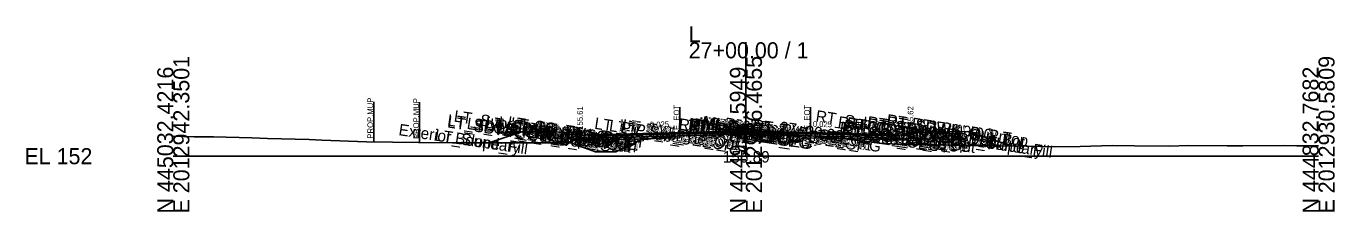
# Model space of a CAD drawing. Extents: x -26 to 4203, y -10 to 9526.
# Drawn here: x 974.3 to 1202.8, y 6990.3 to 7022.7 of the extents above; entities that cross this region are included whole.
import ezdxf

# ---------------------------------------------------------------- set-up
doc = ezdxf.new("R2010")
doc.units = 0
for name, color, linetype in [('Default', 7, 'Continuous'), ('Exist CMT Pavement', 7, 'Continuous'), ('Exist Cross Section Cell', 7, 'Continuous'), ('Exist XS Center Line Elevation Label', 7, 'Continuous'), ('Exist XS Ground Line', 7, 'Continuous'), ('Prop CMT Conc Surface', 7, 'Continuous'), ('Prop CMT Concrete Structures', 7, 'Continuous'), ('Prop CMT Pvmt Course 1', 7, 'Continuous'), ('Prop CMT Pvmt Course 1 CG', 7, 'Continuous'), ('Prop CMT Pvmt Course 1 Wedge', 7, 'Continuous'), ('Prop CMT Pvmt Course 2', 7, 'Continuous'), ('Prop CMT Pvmt Course 2 Wedge', 7, 'Continuous'), ('Prop CMT Pvmt Course 3', 7, 'Continuous'), ('Prop CMT Pvmt Course 3 Wedge', 7, 'Continuous'), ('Prop CMT Pvmt Surface', 7, 'Continuous'), ('Prop CMT Pvmt Wedge Surface 1', 7, 'Continuous'), ('Prop CMT Pvmt Wedge Surface 2', 7, 'Continuous'), ('Prop CMT Pvmt Wedge Surface 3', 7, 'Continuous'), ('Prop CMT Slope Grass', 7, 'Continuous'), ('Prop CMT Subgrade Earthwork', 7, 'Continuous'), ('Prop XS Hydro Elevations', 7, 'Continuous'), ('Prop XS Label Text', 7, 'Continuous'), ('Prop XS SE Text', 7, 'Continuous'), ('Prop XS Side Slope Text', 7, 'Continuous'), ('Scratch_Level_0', 7, 'Continuous')]:
    doc.layers.add(name, color=color, linetype=linetype)

msp = doc.modelspace()

# ---------------------------------------------------------------- linework, layer by layer
at = {"layer": 'Exist CMT Pavement'}
for points in [[(1100, 7003.89), (1099.36, 7003.89), (1099.31, 7003.89), (1099.22, 7003.88), (1097.54, 7003.82), (1097.16, 7003.8), (1095.03, 7003.75), (1092.66, 7003.69), (1092.55, 7003.69), (1092.45, 7003.68), (1090.5, 7003.6), (1090.05, 7003.58), (1090.02, 7003.58), (1089.99, 7003.58), (1088.48, 7003.54)], [(1100, 7003.89), (1100.04, 7003.89), (1100.62, 7003.87), (1102.51, 7003.83), (1104.24, 7003.8), (1105.04, 7003.78), (1105.93, 7003.75), (1107.53, 7003.69), (1108.58, 7003.66), (1110.05, 7003.62), (1110.82, 7003.56), (1111.06, 7003.55), (1111.26, 7003.53), (1111.26, 7003.53)]]:
    msp.add_lwpolyline(points, dxfattribs=at)
at = {"layer": 'Exist Cross Section Cell'}
for p, q in [((1100, 7000), (1100, 7019.86)), ((1000, 7000), (1100, 7000)), ((1100, 7000), (1200, 7000))]:
    msp.add_line(p, q, dxfattribs=at)
at = {"layer": 'Exist XS Ground Line'}
msp.add_lwpolyline([(1000, 7003.5), (1003.67, 7003.39), (1007, 7003.38), (1013.69, 7003.2), (1016.46, 7003.08), (1023.71, 7002.91), (1025.92, 7002.78), (1033.73, 7002.51), (1042.83, 7002.41), (1048.74, 7002.32), (1050.19, 7002.32), (1055.64, 7002.32), (1065.4, 7002.32), (1067.1, 7002.32), (1069.4, 7002.32), (1071.14, 7001.69), (1073.74, 7000.76), (1075.74, 7000.76), (1077.27, 7000.78), (1081.72, 7002.84), (1082.64, 7002.94), (1083.4, 7003.02), (1087.18, 7003.42), (1087.87, 7003.51), (1088.48, 7003.54), (1090.05, 7003.58), (1090.5, 7003.6), (1092.66, 7003.69), (1095.03, 7003.75), (1097.16, 7003.8), (1097.54, 7003.82), (1099.31, 7003.89), (1100.04, 7003.89), (1100.62, 7003.87), (1102.51, 7003.83), (1104.24, 7003.8), (1105.04, 7003.78), (1105.93, 7003.75), (1107.53, 7003.69), (1108.58, 7003.66), (1110.05, 7003.62), (1111.26, 7003.53), (1116.63, 7003.08), (1121.51, 7002.48), (1123.74, 7002.22), (1131, 7001.97), (1139.45, 7001.85), (1143.93, 7001.82), (1148.91, 7001.74), (1153.95, 7001.61), (1158.37, 7001.68), (1163.97, 7001.89), (1167.83, 7001.81), (1173.99, 7001.76), (1177.29, 7001.85), (1184.01, 7001.79), (1186.75, 7001.78), (1194.03, 7001.84), (1196.21, 7001.83), (1200, 7001.81)], dxfattribs=at)
at = {"layer": 'Prop CMT Conc Surface'}
for points in [[(1071.03, 7003.61), (1071.03, 7004.11), (1070.53, 7004.11)], [(1073.04, 7003.74), (1071.03, 7003.61)], [(1126.75, 7003.75), (1128.75, 7003.62)], [(1128.75, 7003.62), (1128.75, 7004.12), (1129.25, 7004.12)], [(1133.25, 7004.21), (1138.25, 7004.31)]]:
    msp.add_lwpolyline(points, dxfattribs=at)
at = {"layer": 'Prop CMT Concrete Structures'}
for points in [[(1102, 7004.36), (1101.99, 7004.53), (1101.24, 7004.78), (1100, 7004.81), (1098.76, 7004.78), (1098.01, 7004.53), (1098, 7004.36)], [(1073.04, 7003.74), (1071.03, 7003.61), (1071.03, 7004.11), (1070.53, 7004.11)], [(1070.53, 7004.11), (1070.53, 7003.09), (1073.04, 7003.16)], [(1073.04, 7003.16), (1073.04, 7003.74)], [(1098, 7004.36), (1100, 7004.41), (1102, 7004.36)], [(1126.75, 7003.75), (1128.75, 7003.62), (1128.75, 7004.12), (1129.25, 7004.12)], [(1129.25, 7004.12), (1129.25, 7003.1), (1126.75, 7003.16)], [(1126.75, 7003.16), (1126.75, 7003.75)], [(1138.25, 7004.31), (1133.25, 7004.21)], [(1133.25, 7004.21), (1133.25, 7003.87)], [(1133.25, 7003.87), (1138.25, 7003.97)], [(1138.25, 7003.97), (1138.25, 7004.31)]]:
    msp.add_lwpolyline(points, dxfattribs=at)
at = {"layer": 'Prop CMT Pvmt Course 1'}
for points in [[(1100, 7004.41), (1073.04, 7003.74)], [(1073.04, 7003.49), (1088.48, 7003.88)], [(1073.04, 7003.74), (1073.04, 7003.49)], [(1088.48, 7004), (1100, 7004.29)], [(1088.48, 7003.88), (1088.48, 7004)], [(1100, 7004.16), (1100, 7004.41)], [(1100, 7004.41), (1126.75, 7003.75)], [(1100, 7004.16), (1100, 7004.41)], [(1100, 7004.29), (1100, 7004.16), (1100, 7004.16)], [(1111.26, 7004.01), (1100, 7004.29)], [(1100, 7004.29), (1100, 7004.16), (1100, 7004.16)], [(1111.26, 7003.88), (1111.26, 7004.01)], [(1126.75, 7003.5), (1111.26, 7003.88)], [(1126.75, 7003.75), (1126.75, 7003.5)]]:
    msp.add_lwpolyline(points, dxfattribs=at)
at = {"layer": 'Prop CMT Pvmt Course 1 CG'}
for points in [[(1073.04, 7003.16), (1070.03, 7003.08), (1069.69, 7002.74)], [(1069.69, 7002.74), (1073.04, 7002.82)], [(1073.04, 7002.82), (1073.04, 7003.16)], [(1126.75, 7003.16), (1129.75, 7003.09), (1130.09, 7002.75)], [(1126.75, 7002.83), (1126.75, 7003.16)], [(1130.09, 7002.75), (1126.75, 7002.83)]]:
    msp.add_lwpolyline(points, dxfattribs=at)
at = {"layer": 'Prop CMT Pvmt Course 1 Wedge'}
for points in [[(1088.48, 7004), (1089.99, 7004.04), (1090.02, 7004.04), (1090.05, 7004.04), (1090.5, 7004.05), (1092.45, 7004.1), (1092.55, 7004.1), (1092.66, 7004.11), (1095.03, 7004.17), (1097.16, 7004.22), (1097.54, 7004.23), (1099.22, 7004.27), (1099.31, 7004.27), (1099.36, 7004.27), (1100, 7004.29)], [(1100, 7004.16), (1099.36, 7004.15), (1099.31, 7004.15), (1099.22, 7004.15), (1097.54, 7004.1), (1097.16, 7004.09), (1095.03, 7004.04), (1092.66, 7003.98), (1092.55, 7003.98), (1092.45, 7003.98), (1090.5, 7003.93), (1090.05, 7003.92), (1090.02, 7003.92), (1089.99, 7003.91), (1088.48, 7003.88)], [(1088.48, 7003.88), (1088.48, 7004)], [(1100, 7004.29), (1100, 7004.16)], [(1100, 7004.29), (1100.04, 7004.29), (1100.62, 7004.27), (1102.51, 7004.23), (1104.24, 7004.18), (1105.04, 7004.16), (1105.93, 7004.14), (1107.53, 7004.1), (1108.58, 7004.08), (1110.05, 7004.04), (1110.82, 7004.02), (1111.06, 7004.01), (1111.26, 7004.01), (1111.26, 7004.01)], [(1100, 7004.16), (1100, 7004.29)], [(1111.26, 7003.88), (1111.26, 7003.88), (1111.06, 7003.89), (1110.82, 7003.89), (1110.05, 7003.91), (1108.58, 7003.95), (1107.53, 7003.98), (1105.93, 7004.02), (1105.04, 7004.04), (1104.24, 7004.06), (1102.51, 7004.1), (1100.62, 7004.15), (1100.04, 7004.16), (1100, 7004.16)], [(1111.26, 7004.01), (1111.26, 7003.88)]]:
    msp.add_lwpolyline(points, dxfattribs=at)
at = {"layer": 'Prop CMT Pvmt Course 2'}
for points in [[(1088.48, 7003.88), (1073.04, 7003.49)], [(1073.04, 7003.16), (1088.48, 7003.54)], [(1073.04, 7003.49), (1073.04, 7003.16)], [(1088.48, 7003.54), (1088.48, 7003.88)], [(1111.26, 7003.55), (1111.26, 7003.88)], [(1111.26, 7003.88), (1126.75, 7003.5)], [(1126.75, 7003.16), (1111.26, 7003.55)], [(1126.75, 7003.5), (1126.75, 7003.16)]]:
    msp.add_lwpolyline(points, dxfattribs=at)
at = {"layer": 'Prop CMT Pvmt Course 2 Wedge'}
for points in [[(1088.48, 7003.88), (1089.99, 7003.91), (1090.02, 7003.92), (1090.05, 7003.92), (1090.5, 7003.93), (1092.45, 7003.98), (1092.55, 7003.98), (1092.66, 7003.98), (1095.03, 7004.04), (1097.16, 7004.09), (1097.54, 7004.1), (1099.22, 7004.15), (1099.31, 7004.15), (1099.36, 7004.15), (1100, 7004.16)], [(1100, 7003.89), (1099.36, 7003.89), (1099.31, 7003.89), (1099.22, 7003.88), (1097.54, 7003.82), (1097.16, 7003.8), (1095.03, 7003.75), (1092.66, 7003.69), (1092.55, 7003.69), (1092.45, 7003.68), (1090.5, 7003.6), (1090.05, 7003.58), (1090.02, 7003.58), (1089.99, 7003.58), (1089.94, 7003.58), (1088.48, 7003.54)], [(1088.48, 7003.54), (1088.48, 7003.88)], [(1100, 7004.16), (1100.04, 7004.16), (1100.62, 7004.15), (1102.51, 7004.1), (1104.24, 7004.06), (1105.04, 7004.04), (1105.93, 7004.02), (1107.53, 7003.98), (1108.58, 7003.95), (1110.05, 7003.91), (1110.82, 7003.89), (1111.06, 7003.89), (1111.26, 7003.88), (1111.26, 7003.88)], [(1100, 7003.89), (1100, 7004.16)], [(1100, 7004.16), (1100, 7003.89)], [(1111.26, 7003.55), (1111.26, 7003.55), (1111.06, 7003.56), (1110.86, 7003.56), (1110.82, 7003.56), (1110.05, 7003.62), (1108.58, 7003.66), (1107.53, 7003.69), (1105.93, 7003.75), (1105.04, 7003.78), (1104.24, 7003.8), (1102.51, 7003.83), (1100.62, 7003.87), (1100.04, 7003.89), (1100, 7003.89)], [(1111.26, 7003.88), (1111.26, 7003.55)]]:
    msp.add_lwpolyline(points, dxfattribs=at)
at = {"layer": 'Prop CMT Pvmt Course 3'}
for points in [[(1088.48, 7003.54), (1073.04, 7003.16)], [(1073.04, 7002.82), (1088.48, 7003.21)], [(1073.04, 7003.16), (1073.04, 7002.82)], [(1088.48, 7003.21), (1088.48, 7003.54)], [(1111.26, 7003.55), (1126.75, 7003.16)], [(1111.26, 7003.22), (1111.26, 7003.55)], [(1126.75, 7002.83), (1111.26, 7003.22)], [(1126.75, 7003.16), (1126.75, 7002.83)]]:
    msp.add_lwpolyline(points, dxfattribs=at)
at = {"layer": 'Prop CMT Pvmt Course 3 Wedge'}
for points in [[(1088.48, 7003.54), (1089.99, 7003.58), (1090, 7003.58)], [(1090, 7003.58), (1089.99, 7003.58), (1088.48, 7003.54)], [(1088.48, 7003.54), (1088.48, 7003.54)], [(1111.26, 7003.53), (1111.26, 7003.53), (1111.06, 7003.55), (1110.87, 7003.56)], [(1110.87, 7003.56), (1111.06, 7003.55)], [(1111.06, 7003.55), (1111.26, 7003.55), (1111.26, 7003.55)], [(1111.26, 7003.55), (1111.26, 7003.53)]]:
    msp.add_lwpolyline(points, dxfattribs=at)
at = {"layer": 'Prop CMT Pvmt Surface'}
for points in [[(1100, 7004.41), (1073.04, 7003.74)], [(1100, 7004.41), (1126.75, 7003.75)]]:
    msp.add_lwpolyline(points, dxfattribs=at)
at = {"layer": 'Prop CMT Pvmt Wedge Surface 1'}
for points in [[(1088.48, 7003.88), (1073.04, 7003.49)], [(1073.04, 7003.49), (1073.04, 7003.74)], [(1100, 7004.29), (1088.48, 7004)], [(1088.48, 7004), (1088.48, 7003.88)], [(1100, 7004.29), (1111.26, 7004.01)], [(1111.26, 7004.01), (1111.26, 7003.88)], [(1111.26, 7003.88), (1126.75, 7003.5)], [(1126.75, 7003.5), (1126.75, 7003.75)]]:
    msp.add_lwpolyline(points, dxfattribs=at)
at = {"layer": 'Prop CMT Pvmt Wedge Surface 2'}
for points in [[(1100, 7004.16), (1073.04, 7003.49)], [(1073.04, 7003.49), (1073.04, 7003.74)], [(1100, 7004.16), (1126.75, 7003.5)], [(1126.75, 7003.5), (1126.75, 7003.75)]]:
    msp.add_lwpolyline(points, dxfattribs=at)
at = {"layer": 'Prop CMT Pvmt Wedge Surface 3'}
for points in [[(1100, 7003.83), (1073.04, 7003.16)], [(1073.04, 7003.16), (1073.04, 7003.74)], [(1100, 7003.83), (1126.75, 7003.16)], [(1126.75, 7003.16), (1126.75, 7003.75)]]:
    msp.add_lwpolyline(points, dxfattribs=at)
at = {"layer": 'Prop CMT Slope Grass'}
for points in [[(1070.53, 7004.11), (1061.03, 7004.3), (1055.09, 7002.32)], [(1129.25, 7004.12), (1138.75, 7004.31), (1146.33, 7001.78)]]:
    msp.add_lwpolyline(points, dxfattribs=at)
at = {"layer": 'Prop CMT Subgrade Earthwork'}
for points in [[(1073.04, 7002.82), (1069.69, 7002.74), (1068.28, 7004.16)], [(1088.48, 7003.21), (1073.04, 7002.82)], [(1088.48, 7003.21), (1088.49, 7003.54)], [(1111.26, 7003.22), (1111.25, 7003.54)], [(1111.26, 7003.22), (1126.75, 7002.83)], [(1126.75, 7002.83), (1130.09, 7002.75), (1131.51, 7004.16)]]:
    msp.add_lwpolyline(points, dxfattribs=at)
at = {"layer": 'Prop XS Label Text'}
for p, q in [((1035, 7009.49), (1035, 7002.49)), ((1043, 7009.41), (1043, 7002.41)), ((1088.48, 7008.54), (1088.48, 7003.54)), ((1111.26, 7008.54), (1111.26, 7003.53))]:
    msp.add_line(p, q, dxfattribs=at)

# ---------------------------------------------------------------- texts
at = {"layer": 'Default'}
msp.add_text('-', height=0.0001, dxfattribs=at).set_placement((1000, 7000))
at = {"layer": 'Exist Cross Section Cell'}
for s, p in [('L', (1090, 7019.86)), ('27+00.00 / 1', (1090, 7017.06)), ('EL 152', (974, 6998.6))]:
    msp.add_text(s, height=2.8, dxfattribs=at).set_placement(p)
for s, p in [('E 2012942.3501', (1002.8, 6990)), ('E 2012936.4655', (1102.8, 6990)), ('E 2012930.5809', (1202.8, 6990)), ('N 445032.4216', (1000, 6990)), ('N 444932.5949', (1100, 6990)), ('N 444832.7682', (1200, 6990))]:
    msp.add_text(s, height=2.8, rotation=90, dxfattribs=at).set_placement(p)
at = {"layer": 'Exist XS Center Line Elevation Label'}
msp.add_text('155.89', height=2, dxfattribs=at).set_placement((1095.97, 6998.89))
at = {"layer": 'Prop XS Hydro Elevations'}
for s, p in [('155.61', (1071.53, 7004.61)), ('155.62', (1129.25, 7004.62))]:
    msp.add_text(s, height=1, rotation=90, dxfattribs=at).set_placement(p)
at = {"layer": 'Prop XS Label Text'}
for s, p in [('PROP.MUP', (1034.9, 7003.07)), ('PROP.MUP', (1042.9, 7002.99)), ('E. EOT', (1088.38, 7004.56)), ('E. EOT', (1111.16, 7004.56))]:
    msp.add_text(s, height=1, rotation=90, dxfattribs=at).set_placement(p)
at = {"layer": 'Prop XS SE Text'}
for rotation, p in [(1.4318, (1083.24, 7005)), (358.5674, (1111.67, 7005.12))]:
    msp.add_text('0.025', height=1, rotation=rotation, dxfattribs=at).set_placement(p)
at = {"layer": 'Prop XS Side Slope Text'}
for rotation, p in [(18.4369, (1057.07, 7003.77)), (341.5699, (1142.03, 7004.01))]:
    msp.add_text('3:1', height=1, rotation=rotation, dxfattribs=at).set_placement(p)
at = {"layer": 'Scratch_Level_0'}
for s, p in [('LT_SDWK_Out_Top', (1047.77, 7005.35)), ('LT_SDWK_Out_Bot', (1047.8, 7005.02)), ('LT_Sub_Trench_Out_DLT', (1048.91, 7006.05)), ('LT_SDWK_In_Top', (1054.38, 7005.01)), ('LT_CG_Top_Face', (1058.29, 7005.01)), ('MI_Face Out', (1092.22, 7004.99)), ('MI_Top Out', (1092.42, 7005.09)), ('RT_Sub_Trench_Out_DLT', (1112.09, 7006.06)), ('RT_CG_Top_Face', (1115.96, 7005.02)), ('RT_CG_Top_BOC', (1117.47, 7004.87)), ('RT_SDWK_In_Top', (1121.05, 7005.03)), ('RT_SDWK_Out_Top', (1124.44, 7005.37)), ('RT_SDWK_Out_Bot', (1124.47, 7005.03)), ('Exterior Boundary', (1039.26, 7003.68)), ('LT_Slope_Fill', (1045.57, 7002.74)), ('LT_CSLP_Pnt', (1051.17, 7004.77)), ('LT_SDWK_In_Bot', (1054.41, 7004.68)), ('LT_CG1_Shelf_Out', (1056.59, 7004.09)), ('27+00.00', (1057.97, 7004.26)), ('LT_CG_Top_BOC', (1058.8, 7004.86)), ('LT_CG_Bot_BOC', (1058.83, 7003.84)), ('LT_CG_Top_Gut', (1059.25, 7004.37)), ('LT_Sub_OEOP', (1059.76, 7003.22)), ('27+00.00', (1060.1, 7004.21)), ('LT_CG_Bot_IE', (1062.91, 7003.67)), ('LT_Sub_OEOT', (1063.08, 7003.31)), ('LT_PV2_OEOT', (1063.17, 7003.96)), ('LT_PV3_OEOT', (1063.17, 7003.63)), ('LT_PV1_OEOT', (1063.73, 7004.13)), ('27+00.00', (1064.13, 7003.98)), ('27+00.00', (1064.42, 7003.65)), ('LT_PV_Sub_Tie_Out', (1073.45, 7004.78)), ('LT_PV_OEEOP_EG', (1076.01, 7004.39)), ('LT_Sub_OEEOP', (1077.66, 7003.82)), ('LT_PV2_OEEOP', (1077.75, 7004.47)), ('LT_PV3_OEEOP', (1077.75, 7004.14)), ('LT_PV1_OEEOP', (1078.31, 7004.52)), ('RT_PV_IEEOP_EG', (1088.12, 7004.66)), ('LT_PV_IEEOP_EG', (1088.17, 7004.65)), ('MI_Face In', (1089.84, 7004.75)), ('RT_PV2_IEEOP', (1089.87, 7004.67)), ('RT_PV3_IEEOP', (1089.87, 7004.34)), ('LT_PV2_IEEOP', (1089.92, 7004.67)), ('LT_PV3_IEEOP', (1089.92, 7004.33)), ('RT_PV1_IEEOP', (1090.43, 7004.71)), ('LT_PV1_IEEOP', (1090.48, 7004.71)), ('MI_Bot In', (1090.81, 7004.43)), ('27+00.00', (1091.1, 7004.46)), ('MI_Top In', (1091.54, 7004.85)), ('MI_Crown', (1093, 7004.85)), ('MI_Bot Out', (1093.21, 7004.67)), ('27+00.00', (1093.69, 7004.82)), ('PV2_PGL', (1093.82, 7004.08)), ('PV1_PGL', (1094.39, 7004.25)), ('27+00.00', (1095.09, 7004.46)), ('MI_Bot', (1095.09, 7004.14)), ('RT_PV_Sub_Tie_Out', (1096.16, 7004.79)), ('RT_PV_OEEOP_EG', (1098.75, 7004.4)), ('RT_Sub_OEEOP', (1100.4, 7003.84)), ('RT_PV2_OEEOP', (1100.49, 7004.49)), ('RT_PV3_OEEOP', (1100.49, 7004.15)), ('RT_PV1_OEEOP', (1101.05, 7004.53)), ('27+00.00', (1105.76, 7004.12)), ('RT_CG1_Shelf_Out', (1116.26, 7004.1)), ('RT_CG_Bot_IE', (1116.58, 7003.68)), ('RT_Sub_OEOT', (1116.74, 7003.32)), ('RT_PV2_OEOT', (1116.84, 7003.97)), ('RT_PV3_OEOT', (1116.84, 7003.64)), ('RT_CG_Top_Gut', (1116.92, 7004.38)), ('RT_PV1_OEOT', (1117.4, 7004.14)), ('RT_CG_Bot_BOC', (1117.5, 7003.85)), ('RT_Sub_OEOP', (1120.12, 7003.23)), ('27+00.00', (1120.82, 7003.71)), ('RT_SDWK_In_Bot', (1121.08, 7004.69)), ('27+00.00', (1122.18, 7004.14)), ('27+00.00', (1125.89, 7004.22)), ('RT_CSLP_Pnt', (1128.84, 7004.78)), ('Exterior Boundary', (1130.5, 7003.14)), ('27+00.00', (1131.72, 7004.33)), ('RT_Slope_Fill', (1136.76, 7002.2))]:
    msp.add_text(s, height=2, rotation=351.4697, dxfattribs=at).set_placement(p)

doc.saveas('drawing.dxf')
